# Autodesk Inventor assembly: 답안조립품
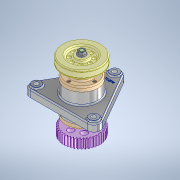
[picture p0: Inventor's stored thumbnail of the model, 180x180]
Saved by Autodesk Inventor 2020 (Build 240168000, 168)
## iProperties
Created: 2023-04
Part Number: 답안조립품
Document SubType Name: Assembly
Designer: home
Author: home
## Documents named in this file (11)
- C:\Users\home\Desktop\730407V1022\답안조립품.iam
- C:\Users\home\Desktop\730407V1022\본체.ipt
- C:\Users\home\Desktop\730407V1022\베어링 6204.ipt
- C:\Users\home\Desktop\730407V1022\축.ipt
- C:\Users\home\Desktop\730407V1022\v-벨트풀리.ipt
- C:\Users\home\Desktop\730407V1022\스퍼기어.ipt
- C:\Users\home\Desktop\730407V1022\커버.ipt
- C:\Users\home\Desktop\730407V1022\오일 실 20 32 8.ipt
- C:\Users\home\Desktop\730407V1022\묻힘키 5x5x16.ipt
- C:\Users\home\Desktop\730407V1022\볼트 M4 x 12.ipt
- C:\Users\home\Desktop\730407V1022\6각 플랜지 너트 M10.ipt
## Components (3 placed, 2 different names)
1. v-벨트풀리:1 — Mate:3, Mate:19, Mate:20, Mate:26
2. 6각 플랜지 너트 M10:1 — Mate:25, Mate:26
3. 6각 플랜지 너트 M10:2 — Mate:27, Mate:28
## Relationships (7: Mate 7)
- Mate:3: v-벨트풀리:1
- Mate:19: v-벨트풀리:1
- Mate:20: v-벨트풀리:1
- Mate:25: 6각 플랜지 너트 M10:1
- Mate:26: v-벨트풀리:1 ↔ 6각 플랜지 너트 M10:1
- Mate:27: 6각 플랜지 너트 M10:2
- Mate:28: 6각 플랜지 너트 M10:2
